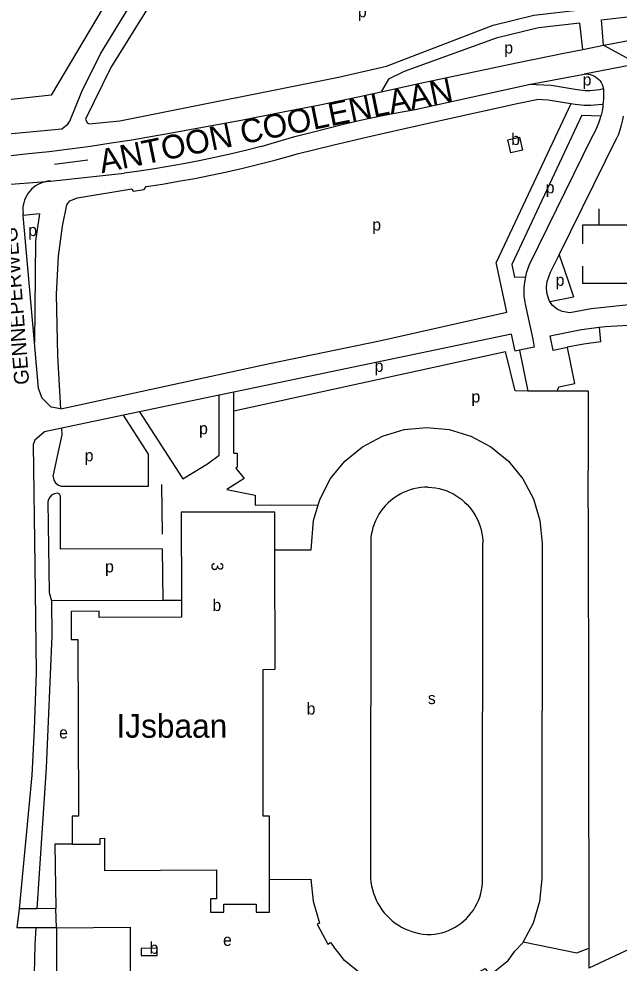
# Model space of a CAD drawing. Extents: x 160204 to 161526, y 379528 to 381793.
# Drawn here: x 160817.1 to 161020.2, y 380595.7 to 380915 of the extents above; entities that cross this region are included whole.
import ezdxf

# ---------------------------------------------------------------- set-up
doc = ezdxf.new("R2010")
doc.units = 0
for name, color, linetype in [('BLT_Basislijn', 7, 'Continuous'), ('BLT_Bebouwing', 7, 'Continuous'), ('BLT_Bebouwing_beschrifting', 7, 'Continuous'), ('BLT_Centroide', 7, 'Continuous'), ('BLT_Huisnummer', 7, 'Continuous'), ('BLT_Onderverdeling_panden', 7, 'Continuous'), ('BLT_Straatnaam', 7, 'Continuous'), ('BLT_Straatnaam_hoofdweg', 7, 'Continuous'), ('BLT_Vlakafsluiter', 7, 'Continuous')]:
    doc.layers.add(name, color=color, linetype=linetype)

msp = doc.modelspace()

# ---------------------------------------------------------------- linework, layer by layer
at = {"layer": 'BLT_Basislijn'}
for p, q in [((161007.93, 380904.7), (161014.88, 380906.09)), ((160989.66, 380892.85), (161008.3, 380896.34)), ((160952.21, 380884.6), (160989.66, 380892.85)), ((160937.5, 380889.86), (160939.69, 380890.34)), ((161003.83, 380886.26), (160978.62, 380832.62)), ((161007.57, 380882.46), (160983.87, 380832.01)), ((161007.57, 380882.46), (161013.99, 380882.19)), ((160999.89, 380835.22), (161019.55, 380875.02)), ((160840.47, 380867.28), (160829.19, 380865.74)), ((160827.74, 380860.18), (160852.66, 380862.89)), ((160859.49, 380857.28), (160860.16, 380858.33)), ((161013.27, 380850.82), (161013.27, 380845.29)), ((160818.58, 380848.56), (160818.52, 380849.21)), ((160824.03, 380849.12), (160818.58, 380848.56)), ((160822.37, 380805.59), (160818.58, 380848.56)), ((161058.35, 380845.29), (161007.77, 380845.29)), ((161007.77, 380845.29), (161007.77, 380838.9)), ((160982.21, 380815.82), (160978.62, 380832.62)), ((160983.87, 380832.01), (160984.79, 380827.67)), ((161007.79, 380831.44), (161007.79, 380825.48)), ((160984.79, 380827.67), (160988.49, 380827.81)), ((161032.39, 380825.52), (161007.79, 380825.48)), ((160996.7, 380819.45), (161004.75, 380820.97)), ((160983.78, 380808.44), (160889.83, 380788.78)), ((160990.98, 380806.66), (160991.41, 380804.01)), ((160991.41, 380804.01), (160986.44, 380802.99)), ((160986.44, 380802.99), (160989.33, 380789.17)), ((160889.83, 380782.43), (160981.78, 380802.57)), ((160831.31, 380783.18), (160901.88, 380798.45)), ((160884.83, 380787.73), (160857.93, 380782.1)), ((160889.83, 380788.78), (160884.83, 380787.73)), ((160884.83, 380767.51), (160884.83, 380787.73)), ((160889.83, 380782.43), (160889.83, 380788.78)), ((160994.88, 380789.15), (160989.33, 380789.17)), ((160999.25, 380789.14), (160994.88, 380789.15)), ((161009.7, 380789.11), (160999.25, 380789.14)), ((161009.7, 380789.11), (161009.7, 380788.71)), ((161009.7, 380788.71), (161009.72, 380762.27)), ((160852.44, 380780.96), (160831.57, 380776.59)), ((160857.93, 380782.1), (160852.44, 380780.96)), ((160889.83, 380768.18), (160889.83, 380782.43)), ((161009.74, 380749.59), (161009.72, 380762.27)), ((160865.34, 380757.53), (160865.52, 380740.76)), ((160826.88, 380751.69), (160827.29, 380721)), ((160897.01, 380750.57), (160902.72, 380750.66)), ((161009.74, 380749.59), (161009.9, 380600.74)), ((160865.57, 380735.77), (160865.76, 380718.31)), ((160827.29, 380721), (160828.11, 380718.27)), ((160865.76, 380718.31), (160828.11, 380718.27)), ((160828.11, 380718.27), (160828.24, 380706.35)), ((160872.11, 380718.32), (160865.76, 380718.31)), ((160829.26, 380635.89), (160829.57, 380614.19)), ((160835.17, 380635.88), (160829.26, 380635.89)), ((160817.13, 380614.04), (160816.35, 380607.67)), ((160823.18, 380614.11), (160817.13, 380614.04)), ((160829.57, 380614.19), (160823.18, 380614.11)), ((160829.82, 380607.64), (160829.57, 380614.19)), ((161041.32, 380608.7), (161009.91, 380593.97)), ((160822.78, 380607.66), (160816.35, 380607.67)), ((160829.82, 380607.64), (160822.78, 380607.66)), ((160829.82, 380607.64), (160854.89, 380607.88)), ((160854.91, 380585.87), (160854.89, 380607.88)), ((161009.9, 380600.74), (161009.91, 380593.97))]:
    msp.add_line(p, q, dxfattribs=at)
for points in [[(160700, 380873.36), (160703, 380873.17), (160752.35, 380872.77), (160791.74, 380874.12), (160831.61, 380877.85), (160833.62, 380879.38), (160834.32, 380880.4), (160838.36, 380890.46), (160844.74, 380903.21), (160870.63, 380945.7), (160886.24, 380974.57), (160895.58, 380993.86), (160904.56, 381013.34), (160914.55, 381038.18), (160916.95, 381044.91)], [(160908.98, 381043.38), (160896.28, 381011.33), (160884.2, 380984.68), (160875.62, 380967.18), (160868.56, 380954.56), (160845.47, 380918.66), (160827.98, 380889.21), (160814.63, 380887.74), (160803.1, 380885.11), (160780.73, 380883.12), (160759.77, 380882.17), (160743.05, 380882.09), (160725.89, 380883.03), (160700, 380885.56)], [(160883.7, 380957.24), (160876.41, 380943.99), (160848.18, 380898.59), (160839.67, 380881.07), (160840.22, 380879.91), (160840.82, 380879.57), (160851.2, 380880.6), (160854.65, 380881.2), (160925.21, 380895.31), (160941.52, 380899.08), (160977.51, 380912.94), (160991.31, 380916.26), (161006.94, 380918.11)], [(161014.88, 380906.09), (161014.24, 380914.74), (161083.94, 380922.92), (161086.58, 380923), (161089.41, 380922.59), (161093.05, 380918.88)], [(161007.93, 380904.7), (161006.82, 380913.55), (160992.84, 380911.96), (160978.57, 380908.46), (160947.45, 380897.24), (160942.15, 380894.67), (160939.69, 380890.34)], [(161014.88, 380906.09), (161017.51, 380906.61), (161033.56, 380909.73), (161036.52, 380910.29)], [(160939.69, 380890.34), (160953.47, 380893.37), (160969.46, 380896.8), (160985.46, 380900.15), (161001.48, 380903.42), (161007.93, 380904.7)], [(161008.3, 380896.34), (161008.99, 380896.39), (161009.67, 380896.35), (161010.35, 380896.24), (161011.01, 380896.04), (161011.64, 380895.77), (161012.23, 380895.43), (161012.79, 380895.03), (161013.29, 380894.56), (161013.73, 380894.04), (161014.11, 380893.47), (161014.42, 380892.86), (161014.66, 380892.21), (161014.82, 380891.55), (161014.84, 380891.34)], [(161014.84, 380891.34), (161013.54, 380891.05), (161010.39, 380890.69), (161008.66, 380890.72), (161005.94, 380890.98), (160997.18, 380892.45), (160989.66, 380892.85)], [(160866.86, 380876.15), (160879.88, 380878.49), (160892.9, 380880.92), (160905.89, 380883.43), (160918.88, 380886.01), (160931.84, 380888.67), (160937.5, 380889.86)], [(161014.84, 380889.59), (161014.84, 380888.15), (161014.77, 380886.71), (161014.71, 380886.19)], [(161014.84, 380891.34), (161014.9, 380890.86), (161014.9, 380890.5)], [(161014.9, 380890.5), (161014.9, 380890.18), (161014.84, 380889.59)], [(160960.16, 380880.77), (160985.69, 380886.37), (160992.32, 380887.76)], [(161003.83, 380886.26), (160996.13, 380887.56), (160992.32, 380887.76)], [(161014.71, 380886.19), (161014.38, 380886.11), (161010.63, 380885.68), (161008.38, 380885.73), (161005.29, 380886.02), (161003.83, 380886.26)], [(161014.71, 380886.19), (161014.61, 380885.28), (161014.38, 380883.86), (161014.06, 380882.46), (161013.99, 380882.19)], [(160899.01, 380871.87), (160904.74, 380873.58), (160910.49, 380875.21), (160916.26, 380876.76), (160922.05, 380878.23), (160927.86, 380879.63), (160933.69, 380880.95), (160939.53, 380882.19), (160945.39, 380883.35), (160951.27, 380884.43), (160952.21, 380884.6)], [(160911.23, 380869.37), (160923.19, 380872.28), (160935.17, 380875.12), (160947.16, 380877.88), (160959.18, 380880.55), (160960.16, 380880.77)], [(161013.99, 380882.19), (161013.67, 380881.08), (161013.21, 380879.72), (161012.66, 380878.39), (161012.05, 380877.09), (161011.36, 380875.82), (161010.89, 380875.04)], [(161021.52, 380882.08), (161021.28, 380880.83), (161020.86, 380879.09), (161020.37, 380877.38), (161019.79, 380875.68), (161019.55, 380875.02)], [(160792.24, 380867.12), (160799.28, 380867.59), (160806.31, 380868.13), (160813.34, 380868.75), (160820.36, 380869.45), (160827.37, 380870.23), (160834.37, 380871.09), (160841.36, 380872.03), (160848.34, 380873.05), (160855.31, 380874.15), (160862.27, 380875.33), (160866.86, 380876.15)], [(161010.89, 380875.04), (160989.69, 380831.82), (160988.76, 380829.08), (160988.49, 380827.81)], [(160899.01, 380871.87), (160893.81, 380870.55), (160888.59, 380869.3), (160883.36, 380868.13), (160878.1, 380867.04), (160872.83, 380866.03), (160867.55, 380865.09), (160862.25, 380864.24), (160856.94, 380863.46), (160852.66, 380862.89)], [(160860.16, 380858.33), (160865.65, 380859.17), (160871.12, 380860.09), (160876.58, 380861.09), (160882.02, 380862.17), (160887.45, 380863.33), (160892.86, 380864.56), (160898.26, 380865.87), (160903.63, 380867.26), (160908.98, 380868.73), (160911.23, 380869.37)], [(160827.74, 380860.18), (160826.86, 380860.1), (160825.99, 380859.93), (160825.14, 380859.69), (160824.31, 380859.37), (160823.52, 380858.98), (160822.76, 380858.51), (160822.05, 380857.99), (160821.39, 380857.39), (160820.79, 380856.75), (160820.25, 380856.05), (160819.77, 380855.3), (160819.36, 380854.52), (160819.02, 380853.7), (160818.76, 380852.85), (160818.58, 380851.98), (160818.47, 380851.1), (160818.45, 380850.22), (160818.5, 380849.34), (160818.52, 380849.21)], [(160836.91, 380854.5), (160855.31, 380857.6), (160855.74, 380856.8), (160859.49, 380857.28)], [(160831.31, 380783.18), (160830.25, 380801.06), (160829.87, 380821.97), (160830.53, 380834.76), (160831.84, 380844.91), (160833.27, 380852.15), (160834.34, 380853.44), (160836.91, 380854.5)], [(160824.03, 380849.12), (160822.72, 380839.91), (160822.37, 380805.59)], [(160995.71, 380825.46), (160995.82, 380826.2), (160996.97, 380829.32), (160999.89, 380835.22)], [(160999.89, 380835.22), (161002.78, 380826.74), (161004.75, 380820.97)], [(160988.49, 380827.81), (160988.1, 380826.02), (160987.9, 380824.1), (160987.96, 380821.27), (160988.34, 380818.56), (160990.98, 380806.66)], [(160996.7, 380819.45), (160996.51, 380819.74), (160995.71, 380822.38), (160995.56, 380824.38), (160995.71, 380825.46)], [(161058.35, 380825.52), (161058.32, 380818.6), (161025.6, 380818.6), (161010.72, 380817), (161003.46, 380815.64), (161000.89, 380816.1), (160999.19, 380816.85), (160997.58, 380818.13), (160996.7, 380819.45)], [(160901.88, 380798.45), (160939.12, 380806.12), (160982.21, 380815.82)], [(160996.8, 380807.87), (160999.01, 380808.34), (161007.39, 380810), (161013.45, 380810.74)], [(161013.45, 380810.74), (161013.92, 380805.76), (161008.19, 380805.06), (161002.63, 380803.96)], [(161013.45, 380810.74), (161015.46, 380810.99), (161023.36, 380811.42), (161028.07, 380811.43)], [(160986.44, 380802.99), (160985.01, 380802.7), (160983.78, 380808.44)], [(160999.25, 380789.14), (160999.75, 380790.57), (161005.17, 380791.71), (161002.65, 380803.89), (160997.83, 380802.89), (160996.8, 380807.87)], [(160831.31, 380783.18), (160827.96, 380783.75), (160824.93, 380786.76), (160823.74, 380790.06), (160822.37, 380805.59)], [(160989.33, 380789.17), (160984.95, 380789.18), (160981.78, 380802.57)], [(160828.69, 380760.25), (160828.9, 380758.99), (160829.45, 380758.1), (160830.44, 380757.33), (160831.34, 380757), (160860.99, 380757.05), (160860.97, 380767.84), (160852.44, 380780.96)], [(160857.93, 380782.1), (160872.51, 380759.46), (160880.92, 380764.58), (160884.83, 380767.51)], [(160831.57, 380776.59), (160825.72, 380775.36), (160822.43, 380772.59), (160821.93, 380771.11), (160822.52, 380730.33), (160822.98, 380693.94), (160822.22, 380674.7), (160821.49, 380659.25), (160817.13, 380614.04)], [(160828.69, 380760.25), (160830.5, 380768.76), (160831.69, 380774.36), (160831.57, 380776.59)], [(160889.83, 380768.18), (160890.91, 380768.19), (160890.89, 380763.42), (160890.5, 380763.04), (160893.31, 380759.61), (160887.49, 380755.88), (160897.03, 380753.96), (160897.01, 380750.57)], [(160865.57, 380735.77), (160831.18, 380735.73), (160831.12, 380753.61), (160830.83, 380754.34), (160830.11, 380754.58), (160829.12, 380754.43), (160828.27, 380754.04), (160827.57, 380753.33), (160827.12, 380752.48), (160826.88, 380751.69)], [(160902.72, 380750.66), (160904.98, 380750.61), (160918.35, 380750.63)], [(160828.24, 380706.35), (160826.36, 380661.73), (160823.92, 380625.98), (160823.18, 380614.11)], [(160822.78, 380607.66), (160822.43, 380602.05), (160822.22, 380592.04), (160824.34, 380580.98), (160826.47, 380570.97), (160825.93, 380559.53)], [(160829.82, 380607.64), (160829.75, 380576.44), (160846.4, 380575.22), (160844.84, 380556.91)], [(160987.67, 380602.91), (161005.82, 380599.21), (161009.9, 380600.74)]]:
    msp.add_lwpolyline(points, dxfattribs=at)
at = {"layer": 'BLT_Bebouwing'}
for p, q in [((160936.18, 380739.61), (160936.06, 380625.66)), ((160973.95, 380623.63), (160974.03, 380737.84)), ((160835.17, 380635.88), (160844.59, 380635.91)), ((160925.82, 380598.54), (160923.64, 380601.21))]:
    msp.add_line(p, q, dxfattribs=at)
for points in [[(160982.46, 380874.1), (160986.46, 380875.03), (160987.48, 380870.66), (160983.48, 380869.72), (160982.46, 380874.1)], [(160918.35, 380750.63), (160919, 380752.75), (160922.57, 380759.55), (160927.39, 380765.42), (160933.34, 380770.3), (160940.11, 380773.92), (160947.44, 380776.12), (160955.07, 380776.88), (160962.72, 380776.11), (160970.03, 380773.9), (160976.77, 380770.28), (160982.71, 380765.41), (160987.54, 380759.49), (160991.17, 380752.7), (160993.39, 380745.38), (160994.11, 380737.75), (160994.04, 380624.17), (160993.27, 380616.56), (160991.05, 380609.22), (160987.67, 380602.91)], [(160955.58, 380756.68), (160954.34, 380756.65), (160953.1, 380756.55), (160951.87, 380756.36), (160950.65, 380756.1), (160949.46, 380755.75), (160948.29, 380755.34), (160947.15, 380754.84), (160946.04, 380754.28), (160944.97, 380753.64), (160943.94, 380752.94), (160942.96, 380752.17), (160942.04, 380751.35), (160941.17, 380750.46), (160940.35, 380749.52), (160939.6, 380748.53), (160938.92, 380747.49), (160938.3, 380746.41), (160937.75, 380745.3), (160937.28, 380744.15), (160936.88, 380742.97), (160936.56, 380741.77), (160936.31, 380740.55), (160936.18, 380739.61)], [(160955.58, 380756.68), (160956.81, 380756.6), (160958.04, 380756.44), (160959.25, 380756.2), (160960.44, 380755.88), (160961.61, 380755.49), (160962.76, 380755.02), (160963.87, 380754.48), (160964.94, 380753.86), (160965.97, 380753.18), (160966.95, 380752.44), (160967.89, 380751.63), (160968.77, 380750.76), (160969.59, 380749.84), (160970.35, 380748.86), (160971.05, 380747.84), (160971.68, 380746.78), (160972.24, 380745.68), (160972.72, 380744.54), (160973.13, 380743.38), (160973.47, 380742.19), (160973.73, 380740.98), (160973.91, 380739.76), (160974.01, 380738.53), (160974.03, 380737.84)], [(160903.67, 380735.42), (160915.94, 380735.47), (160916.76, 380745.42), (160918.35, 380750.63)], [(160903.67, 380735.42), (160903.64, 380748.23), (160872.03, 380748.15), (160872.11, 380718.32)], [(160872.11, 380718.32), (160872.12, 380712.71), (160844.27, 380712.63), (160844.27, 380714.67), (160834.8, 380714.65), (160834.83, 380706.45)], [(160834.83, 380706.45), (160834.83, 380705.16), (160837.05, 380705.16), (160837.17, 380676.84), (160837.3, 380645.37), (160835.14, 380645.37), (160835.17, 380635.88)], [(160844.59, 380635.91), (160844.59, 380637.89), (160846.07, 380637.9), (160846.09, 380627.05)], [(160846.09, 380627.05), (160883.92, 380627.21), (160883.95, 380617.47), (160881.95, 380617.47), (160881.97, 380612.95), (160886.45, 380612.96), (160886.44, 380615.6), (160897.37, 380615.63), (160897.38, 380612.96), (160901.88, 380612.97), (160901.85, 380624.03)], [(160936.06, 380625.66), (160936.1, 380624.38), (160936.22, 380623.12), (160936.42, 380621.86), (160936.7, 380620.61), (160937.05, 380619.39), (160937.49, 380618.19), (160937.99, 380617.02), (160938.57, 380615.89), (160939.22, 380614.79), (160939.94, 380613.74), (160940.72, 380612.73), (160941.56, 380611.77), (160942.46, 380610.87), (160943.42, 380610.03), (160944.42, 380609.25), (160945.48, 380608.53), (160946.58, 380607.88), (160947.71, 380607.3), (160948.88, 380606.8), (160950.08, 380606.36), (160951.3, 380606.01), (160952.55, 380605.73), (160953.8, 380605.53), (160955.07, 380605.41), (160956.35, 380605.37), (160956.57, 380605.37)], [(160901.85, 380624.03), (160915.92, 380624.06), (160916.62, 380616.63), (160918.85, 380609.24), (160917.98, 380608.87), (160921.62, 380602.07), (160922.48, 380602.64), (160923.64, 380601.21)], [(160956.57, 380605.37), (160957.79, 380605.49), (160958.99, 380605.69), (160960.18, 380605.97), (160961.35, 380606.33), (160962.49, 380606.76), (160963.6, 380607.27), (160964.68, 380607.85), (160965.71, 380608.49), (160966.7, 380609.21), (160967.64, 380609.99), (160968.53, 380610.82), (160969.37, 380611.72), (160970.14, 380612.66), (160970.85, 380613.66), (160971.49, 380614.7), (160972.06, 380615.77), (160972.56, 380616.89), (160972.99, 380618.03), (160973.34, 380619.2), (160973.61, 380620.39), (160973.8, 380621.6), (160973.92, 380622.81), (160973.95, 380623.63)], [(160987.67, 380602.91), (160987.43, 380602.45), (160984.9, 380599.74)], [(160858.43, 380600.66), (160858.45, 380598.26), (160863.93, 380598.31), (160863.9, 380600.71), (160858.43, 380600.66)], [(160959.47, 380585.59), (160954.9, 380585.12), (160947.29, 380585.86), (160939.96, 380588.12), (160933.21, 380591.74), (160927.27, 380596.64), (160925.82, 380598.54)], [(160959.47, 380585.59), (160962.73, 380585.93), (160962.21, 380588.67), (160968.83, 380590.63), (160974.9, 380593.9), (160976.46, 380591.59), (160982.58, 380596.63), (160984.9, 380599.74)]]:
    msp.add_lwpolyline(points, dxfattribs=at)
at = {"layer": 'BLT_Onderverdeling_panden'}
msp.add_lwpolyline([(160901.85, 380624.03), (160901.84, 380645.42), (160899.76, 380645.42), (160899.7, 380695.05), (160903.78, 380695.06), (160903.67, 380735.42)], dxfattribs=at)
at = {"layer": 'BLT_Vlakafsluiter'}
for p, q in [((161014.88, 380906.09), (161026.47, 380899.79)), ((161026.47, 380899.79), (161008.3, 380896.34)), ((160798.1, 380857.8), (160827.74, 380860.18))]:
    msp.add_line(p, q, dxfattribs=at)

# ---------------------------------------------------------------- texts
at = {"layer": 'BLT_Bebouwing_beschrifting'}
msp.add_text('IJsbaan', height=8, dxfattribs=at).set_placement((160850.11, 380671.91))
at = {"layer": 'BLT_Centroide'}
for s, p in [('p', (160931.79, 380915.57)), ('p', (160981.31, 380903.3)), ('p', (161007.83, 380892.5)), ('b', (160983.64, 380872.38)), ('p', (160995.34, 380856.03)), ('p', (160820.27, 380841.58)), ('p', (160936.64, 380843.45)), ('p', (160998.69, 380824.73)), ('p', (160937.46, 380795.66)), ('p', (160970.2, 380785.29)), ('p', (160878.06, 380774.55)), ('p', (160839.36, 380765.41)), ('p', (160846.25, 380727.83)), ('b', (160882.58, 380714.77)), ('s', (160955.46, 380683.29)), ('b', (160914.45, 380679.77)), ('e', (160830.71, 380671.67)), ('b', (160861.31, 380598.84)), ('e', (160886.16, 380601.54))]:
    msp.add_text(s, height=4, dxfattribs=at).set_placement(p)
at = {"layer": 'BLT_Huisnummer'}
msp.add_text('3', height=4, rotation=272, dxfattribs=at).set_placement((160882.21, 380731.26))
at = {"layer": 'BLT_Straatnaam'}
msp.add_text('GENNEPERWEG', height=5, rotation=94.4963, dxfattribs=at).set_placement((160820.61, 380791.49))
at = {"layer": 'BLT_Straatnaam_hoofdweg'}
msp.add_text('ANTOON COOLENLAAN', height=8, rotation=11.589, dxfattribs=at).set_placement((160845.11, 380862.81))

doc.saveas('drawing.dxf')
